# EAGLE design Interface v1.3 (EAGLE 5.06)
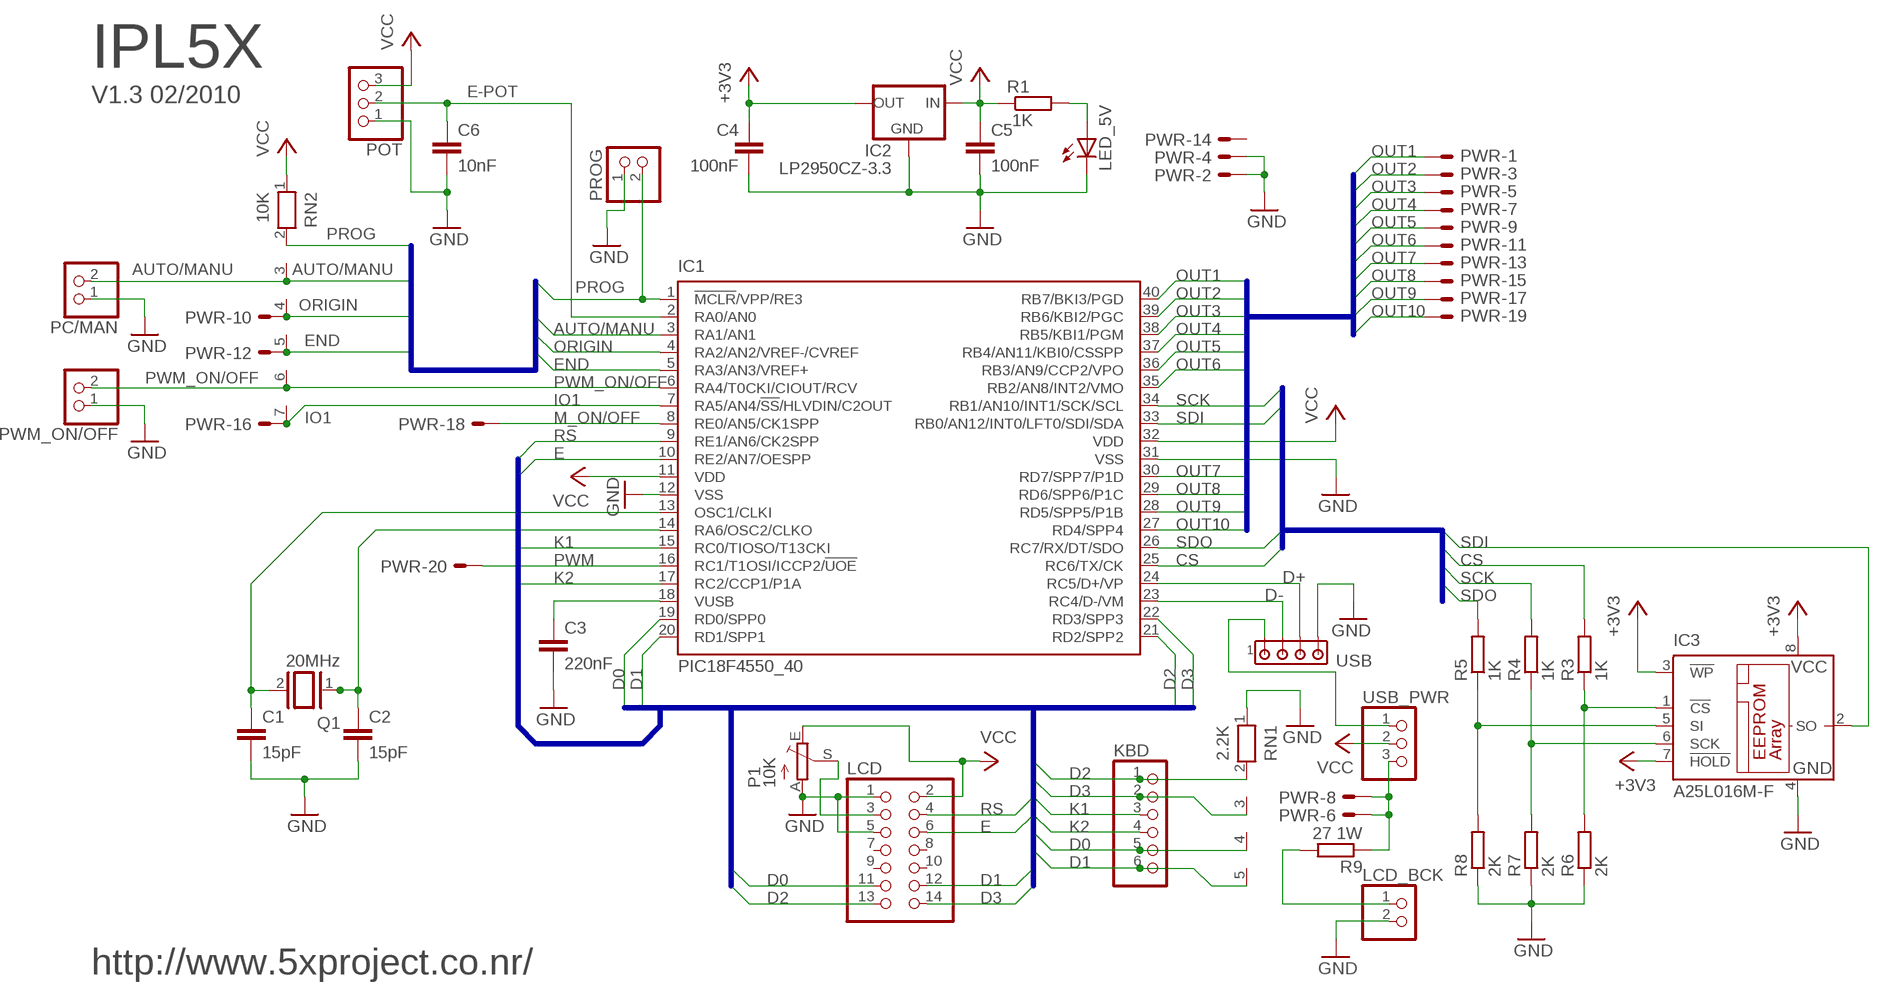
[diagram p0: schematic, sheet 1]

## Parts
C1  15pF  C-EU025-024X044  [C025-024X044]
C2  15pF  C-EU025-024X044  [C025-024X044]
C3  220nF  C-EU050-030X075  [C050-030X075]
C4  100nF  C-EU075-032X103  [C075-032X103]
C5  100nF  C-EU050-030X075  [C050-030X075]
C6  10nF  C-EU050-030X075  [C050-030X075]
IC1  PIC18F4550_40  [DIL40]
IC2  LP2950CZ-3.3  LP2950ACZ-3.3  [TO92]
IC3  A25L016M-F  25LC080SN  [SO-08]
KBD  PINHD-1X6  [1X06]
LCD  PINHD-2X7  [2X07]
LCD_BCK  PINHD-1X2  [1X02]
LED_5V  LED5MM  [LED5MM]
P1  10K  TRIM_EU-LI10  [LI10]
PC/MAN  PINHD-1X2  [1X02]
POT  PINHD-1X3  [1X03]
PROG  PINHD-1X2  [1X02]
PWM_ON/OFF  PINHD-1X2  [1X02]
PWR  ML20E  [ML20]
Q1  20MHz  XTAL/S  [QS]
R1  1K  R-EU_0207/10  [0207/10]
R3  1K  R-EU_0207/10  [0207/10]
R4  1K  R-EU_0207/10  [0207/10]
R5  1K  R-EU_0207/10  [0207/10]
R6  2K  R-EU_0204/7  [0204/7]
R7  2K  R-EU_0204/7  [0204/7]
R8  2K  R-EU_0204/7  [0204/7]
R9  27 1W  R-EU_0207/12  [0207/12]
RN1  2.2K  RN04  [RN-5]
RN2  10K  RN06  [RN-7]
USB  MTA04-100  [10X04MTA]
USB_PWR  PINHD-1X3  [1X03]

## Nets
+3V3: C4.1 IC2.1(OUT) IC3.3(!WP) IC3.7(!HOLD) IC3.8(VCC)
AUTO/MANU: IC1.3(RA1/AN1) PC/MAN.2 RN2.3
CS: IC1.25(RC6/TX/CK) R3.2
D0: IC1.19(RD0/SPP0) KBD.5 LCD.11 RN1.4
D1: IC1.20(RD1/SPP1) KBD.6 LCD.12 RN1.5
D2: IC1.21(RD2/SPP2) KBD.1 LCD.13 RN1.2
D3: IC1.22(RD3/SPP3) KBD.2 LCD.14 RN1.3
D+: IC1.24(RC5/D+/VP) USB.3
D-: IC1.23(RC4/D-/VM) USB.2
E: IC1.10(RE2/AN7/OESPP) LCD.6
E-POT: C6.1 IC1.2(RA0/AN0) POT.2
END: IC1.5(RA3/AN3/VREF+) PWR.12 RN2.5
GND: C1.2 C2.2 C3.2 C4.2 C5.2 C6.2 IC1.12(VSS) IC1.31(VSS) IC2.2(GND) IC3.4(GND) LCD.1 LCD.5 LCD_BCK.2 LED_5V.K(C) P1.A PC/MAN.1 POT.1 PROG.1 PWM_ON/OFF.1 PWR.2 PWR.4 R6.1 R7.1 R8.1 RN1.1 USB.4
IO1: IC1.7(RA5/AN4/!SS!/HLVDIN/C2OUT) PWR.16 RN2.7
K1: IC1.15(RC0/TIOSO/T13CKI) KBD.3
K2: IC1.17(RC2/CCP1/P1A) KBD.4
M_ON/OFF: IC1.8(RE0/AN5/CK1SPP) PWR.18
N$1: C2.1 IC1.14(RA6/OSC2/CLKO) Q1.1
N$2: C1.1 IC1.13(OSC1/CLKI) Q1.2
N$5: PWR.6 PWR.8 R9.1 USB_PWR.3
N$6: LED_5V.A R1.2
N$7: C3.1 IC1.18(VUSB)
N$8: IC3.1(!CS) R3.1 R6.2
N$10: IC3.6(SCK) R4.1 R7.2
N$11: USB.1 USB_PWR.1
N$12: LCD_BCK.1 R9.2
N$14: IC3.5(SI) R5.1 R8.2
N$16: LCD.3 P1.S
ORIGIN: IC1.4(RA2/AN2/VREF-/CVREF) PWR.10 RN2.4
OUT1: IC1.40(RB7/BKI3/PGD) PWR.1
OUT2: IC1.39(RB6/KBI2/PGC) PWR.3
OUT3: IC1.38(RB5/KBI1/PGM) PWR.5
OUT4: IC1.37(RB4/AN11/KBI0/CSSPP) PWR.7
OUT5: IC1.36(RB3/AN9/CCP2/VPO) PWR.9
OUT6: IC1.35(RB2/AN8/INT2/VMO) PWR.11
OUT7: IC1.30(RD7/SPP7/P1D) PWR.13
OUT8: IC1.29(RD6/SPP6/P1C) PWR.15
OUT9: IC1.28(RD5/SPP5/P1B) PWR.17
OUT10: IC1.27(RD4/SPP4) PWR.19
PROG: IC1.1(!MCLR!/VPP/RE3) PROG.2 RN2.2
PWM: IC1.16(RC1/T1OSI/ICCP2/!UOE) PWR.20
PWM_ON/OFF: IC1.6(RA4/T0CKI/CIOUT/RCV) PWM_ON/OFF.2 RN2.6
RS: IC1.9(RE1/AN6/CK2SPP) LCD.4
SCK: IC1.34(RB1/AN10/INT1/SCK/SCL) R4.2
SDI: IC1.33(RB0/AN12/INT0/LFT0/SDI/SDA) IC3.2(SO)
SDO: IC1.26(RC7/RX/DT/SDO) R5.2
VCC: C5.1 IC1.11(VDD) IC1.32(VDD) IC2.3(IN) LCD.2 P1.E POT.3 R1.1 RN2.1 USB_PWR.2
Unconnected: LCD.7 LCD.8 LCD.9 LCD.10 PWR.14

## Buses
OUT1,OUT2,OUT3,OUT4,OUT5,OUT6,OUT7,OUT8,OUT9,OUT10
SDI,SDO,SCK,CS
PROG,AUTO/MANU,ORIGIN,END,M_ON/OFF
D0,D1,D2,D3,E,RS,K1,K2

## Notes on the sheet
- IPL5X
- V1.3 02/2010
- http://www.5xproject.co.nr/

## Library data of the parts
C1-C6 = rcl:C-EU: CAPACITOR, European symbol
IC1 = microchip:PIC18F4*_40: USB Microcontrollers with nanoWatt Technology High-Performance, Enhanced Flash, 28/40/44-Pin, Source: http://ww1.microchip.com/downloads/en/devicedoc/39632c.pdf
IC2 = v-reg:LP2950?*: Source: http://cache.national.com/ds/LP/LP2950.pdf
IC3 = microchip:25*: Serial EEPROM 4 K, SPI bus
KBD = pinhead:PINHD-1X6: PIN HEADER
LCD = pinhead:PINHD-2X7: PIN HEADER
LCD_BCK PC/MAN PROG PWM_ON/OFF = pinhead:PINHD-1X2: PIN HEADER
LED_5V = led:LED: LED
P1 = pot:TRIM_EU-: POTENTIOMETER
POT USB_PWR = pinhead:PINHD-1X3: PIN HEADER
PWR = con-harting-ml:ML20?E: HARTING
Q1 = special:XTAL/S: CRYSTAL
R1 R3-R9 = rcl:R-EU_: RESISTOR, European symbol
RN1 = resistor-net:RN04: RESISTOR NETWORK
RN2 = resistor-net:RN06: RESISTOR NETWORK
USB = con-amp:MTA04-100: AMP connector

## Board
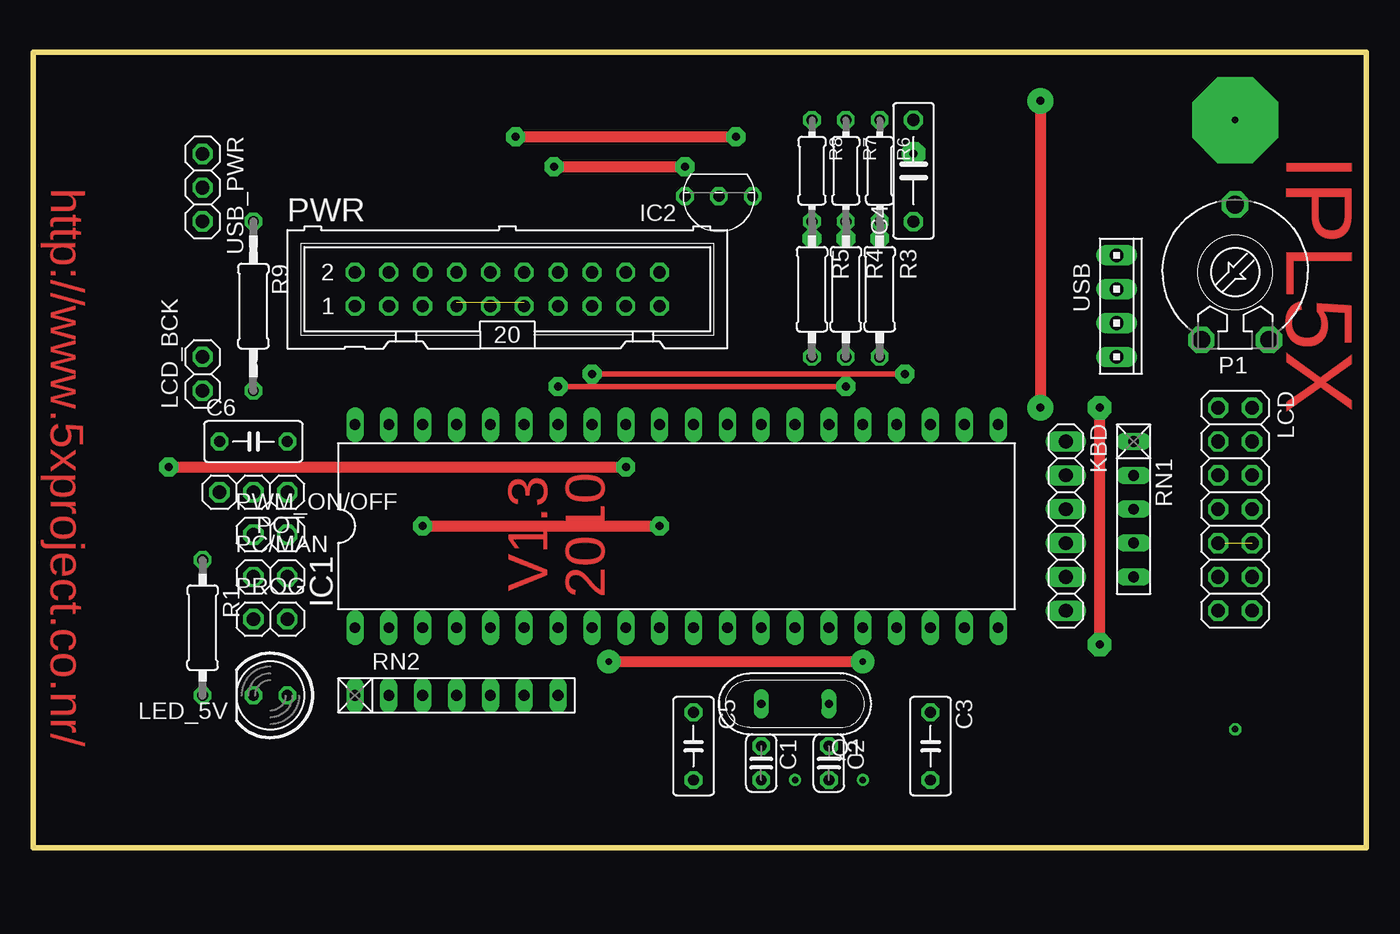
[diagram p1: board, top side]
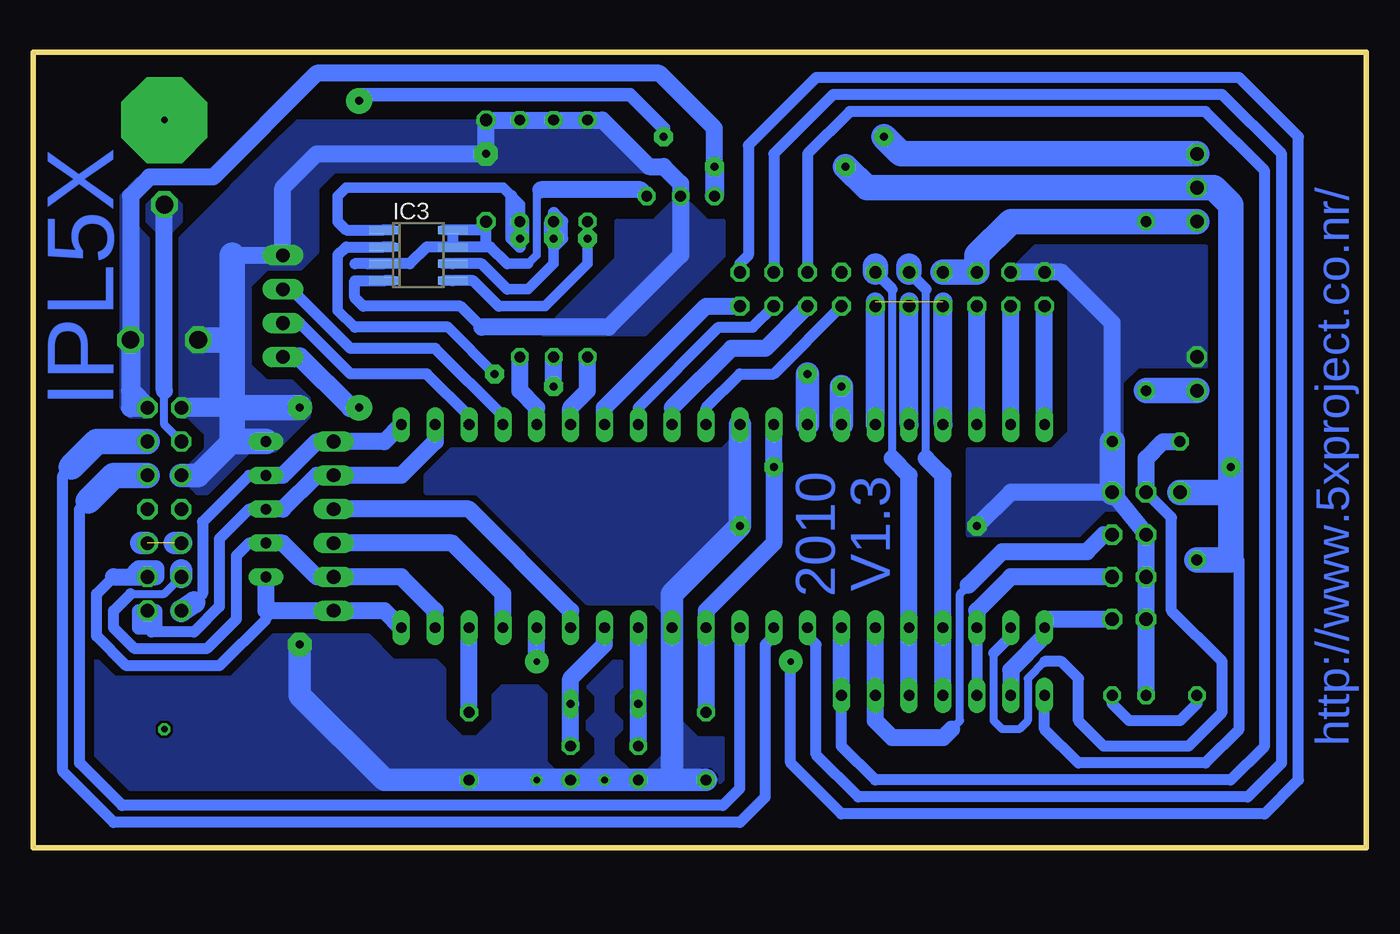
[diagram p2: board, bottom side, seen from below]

Size 100 x 59.68 mm. Coordinates in mm from the lower left corner, seen from the top.
Outline: 0,0 100,0 100,59.68 0,59.68 0,0
Copper layers (1*16): Top 0.035mm / dielectric 1.5mm / Bottom 0.035mm
Design rules "default": minimum track width 10mil, minimum drill 24mil, track to track 8mil, track to pad 8mil, pad to pad 8mil, via to via 8mil, smd to smd 8mil, copper to edge 40mil, drill to drill 8mil, minimum pad ring 10mil, minimum via ring 8mil, stop-mask expansion 4mil, vias tented up to drill 0mil, thermal gap 10mil

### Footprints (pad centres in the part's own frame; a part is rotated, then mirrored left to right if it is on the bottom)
C025-024X044 = drill 0.813 octagon: 1 -1.27,0; 2 1.27,0
C050-030X075 = drill 0.813 octagon: 1 -2.54,0; 2 2.54,0
C075-032X103 = drill 0.914 octagon: 1 -3.81,0; 2 3.81,0
DIL40 = drill 0.813 long: 1 -24.13,-7.62; 2 -21.59,-7.62; 3 -19.05,-7.62; 4 -16.51,-7.62; 5 -13.97,-7.62; 6 -11.43,-7.62; 7 -8.89,-7.62; 8 -6.35,-7.62; 9 -3.81,-7.62; 10 -1.27,-7.62; 11 1.27,-7.62; 12 3.81,-7.62; 13 6.35,-7.62; 14 8.89,-7.62; 15 11.43,-7.62; 16 13.97,-7.62; 17 16.51,-7.62; 18 19.05,-7.62; 19 21.59,-7.62; 20 24.13,-7.62; 21 24.13,7.62; 22 21.59,7.62; 23 19.05,7.62; 24 16.51,7.62; 25 13.97,7.62; 26 11.43,7.62; 27 8.89,7.62; 28 6.35,7.62; 29 3.81,7.62; 30 1.27,7.62; 31 -1.27,7.62; 32 -3.81,7.62; 33 -6.35,7.62; 34 -8.89,7.62; 35 -11.43,7.62; 36 -13.97,7.62; 37 -16.51,7.62; 38 -19.05,7.62; 39 -21.59,7.62; 40 -24.13,7.62
TO92 = drill 0.813 octagon: 1 -2.54,0; 2 0,0; 3 2.54,0
SO-08 = smd 0.6 x 2.2: 1 -1.905,-2.6; 2 -0.635,-2.6; 3 0.635,-2.6; 4 1.905,-2.6; 5 1.905,2.6; 6 0.635,2.6; 7 -0.635,2.6; 8 -1.905,2.6
1X06 = drill 1.016 long: 1 -6.35,0; 2 -3.81,0; 3 -1.27,0; 4 1.27,0; 5 3.81,0; 6 6.35,0
2X07 = drill 1.016 octagon: 1 -7.62,-1.27; 2 -7.62,1.27; 3 -5.08,-1.27; 4 -5.08,1.27; 5 -2.54,-1.27; 6 -2.54,1.27; 7 0,-1.27; 8 0,1.27; 9 2.54,-1.27; 10 2.54,1.27; 11 5.08,-1.27; 12 5.08,1.27; 13 7.62,-1.27; 14 7.62,1.27
1X02 = drill 1.016 octagon: 1 -1.27,0; 2 1.27,0
LED5MM = drill 0.813 octagon: A -1.27,0; K 1.27,0
LI10 = drill 1.321 octagon: A -2.54,-5.08; E 2.54,-5.08; S 0,5.08
1X03 = drill 1.016 octagon: 1 -2.54,0; 2 0,0; 3 2.54,0
ML20 = drill 0.914 octagon: 1 -11.43,-1.27; 2 -11.43,1.27; 3 -8.89,-1.27; 4 -8.89,1.27; 5 -6.35,-1.27; 6 -6.35,1.27; 7 -3.81,-1.27; 8 -3.81,1.27; 9 -1.27,-1.27; 10 -1.27,1.27; 11 1.27,-1.27; 12 1.27,1.27; 13 3.81,-1.27; 14 3.81,1.27; 15 6.35,-1.27; 16 6.35,1.27; 17 8.89,-1.27; 18 8.89,1.27; 19 11.43,-1.27; 20 11.43,1.27
QS = drill 0.61 long: 1 -2.54,0; 2 2.54,0
0207/10 = drill 0.813 octagon: 1 -5.08,0; 2 5.08,0
0204/7 = drill 0.813 octagon: 1 -3.81,0; 2 3.81,0
0207/12 = drill 0.813 octagon: 1 -6.35,0; 2 6.35,0
RN-5 = drill 0.813 long: 1 -5.08,0; 2 -2.54,0; 3 0,0; 4 2.54,0; 5 5.08,0
RN-7 = drill 0.813 long: 1 -7.62,0; 2 -5.08,0; 3 -2.54,0; 4 0,0; 5 2.54,0; 6 5.08,0; 7 7.62,0
10X04MTA = drill 1.016 long: 1 3.81,0; 2 1.27,0; 3 -1.27,0; 4 -3.81,0

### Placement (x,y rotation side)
C1  54.61,6.35 270 top
C2  59.69,6.35 270 top
C3  67.31,7.62 270 top
C4  66.04,50.8 90 top
C5  49.53,7.62 270 top
C6  16.51,30.48 0 top
IC1  48.26,24.13 0 top
IC2  51.44,48.9 180 top
IC3  71.12,44.45 270 bottom
KBD  77.47,24.13 270 top
LCD  90.17,25.4 270 top
LCD_BCK  12.7,35.56 90 top
LED_5V  17.78,11.43 180 top
P1  90.17,43.18 0 top
PC/MAN  17.78,20.32 0 top
POT  16.51,26.67 180 top
PROG  17.78,17.14 0 top
PWM_ON/OFF  17.78,23.5 0 top
PWR  35.56,41.91 0 top
Q1  57.15,10.79 180 top
R1  12.7,16.51 270 top
R3  63.5,41.91 270 top
R4  60.96,41.91 270 top
R5  58.42,41.91 270 top
R6  63.5,50.8 270 top
R7  60.96,50.8 270 top
R8  58.42,50.8 270 top
R9  16.51,40.64 270 top
RN1  82.55,25.4 270 top
RN2  31.75,11.43 0 top
USB  81.28,40.64 270 top
USB_PWR  12.7,49.53 270 top

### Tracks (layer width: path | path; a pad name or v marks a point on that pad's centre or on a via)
+3V3
  Bottom 0.61: 61.91,49.37 62.23,49.37 62.23,44.45 62.87,43.81
  Bottom 0.8: 62.87,43.81 64.45,43.81
  Bottom 0.813: IC3.7 IC3.8 | IC3.7 70.48,45.09 71.75,43.81 74.93,43.81 | 74.93,43.81 IC3.3 | 64.45,43.81 65.72,45.09 | 65.72,45.09 IC3.7 | 65.72,45.09 66.04,45.09 C4.1 | 74.93,43.81 75.88,43.81
  Bottom 1.27: IC2.1 54.45,49.37 61.91,49.37
AUTO/MANU
  Bottom 0.813: IC1.3 RN2.3
  Bottom 1.27: IC1.3 29.21,17.78 26.67,20.32 PC/MAN.2
CS
  Bottom 1.27: IC1.25 62.23,33.02 63.5,34.29 R3.2
D0
  Bottom 0.61: 92.71,19.05 90.17,19.05 LCD.11
  Bottom 0.813: 92.71,19.05 93.98,17.78 93.98,16.51 92.39,14.92 87,14.92 84.77,17.14 84.77,21.91 83.82,22.86 RN1.4
  Bottom 1.27: IC1.19 69.85,17.78 72.39,20.32 KBD.5 78.74,20.32 81.28,22.86 RN1.4
  Bottom 1.676: LCD.11 88.9,20.8
D1
  Bottom 0.813: 93.98,20.32 95.25,19.05 95.25,15.88 93.03,13.65 86.04,13.65 82.55,17.14 82.55,17.78
  Bottom 1.27: 92.71,20.32 92.08,20.32 90.81,20.32 90.81,20.95 92.08,20.95 92.71,20.32 | IC1.20 73.66,17.78 KBD.6 82.55,17.78 RN1.5 | 92.71,20.32 LCD.12 | 93.98,20.32 92.71,20.32
D2
  Bottom 0.813: RN1.2 83.82,27.94 87.31,24.45 87.31,19.05 87.95,18.41
  Bottom 1.27: IC1.21 73.66,30.48 KBD.1 78.74,30.48 81.28,27.94 RN1.2
  Bottom 1.676: 87.95,18.41 LCD.13
D3
  Bottom 0.813: 90.81,16.51 91.12,16.19 87.95,16.19 86.04,18.1 86.04,23.18 83.82,25.4 RN1.3
  Bottom 1.016: 90.81,16.51 92.08,16.51 92.08,17.78 LCD.14 90.81,17.78 90.81,16.51
  Bottom 1.27: IC1.22 69.85,30.48 72.39,27.94 KBD.2 78.74,27.94 81.28,25.4 RN1.3
D+
  Bottom 0.406: IC1.24 64.77,32.38
  Bottom 0.813: 64.77,32.38 69.85,37.47 76.2,37.47 80.64,41.91 USB.3
D-
  Bottom 0.813: USB.2 80.01,39.37 76.2,35.56 70.48,35.56 67.31,32.38 IC1.23
E
  Bottom 0.813: IC1.10 46.99,4.45 48.26,3.17 93.34,3.17 96.52,6.35 96.52,25.4 95.89,26.04
  Bottom 1.93: 95.89,26.04 93.98,27.94 LCD.6
E-POT
  Bottom 0.61: 24.13,13.97 25.4,12.7 25.4,9.53 26.04,8.89 27.3,8.89 27.94,9.53 27.94,14.61
  Bottom 0.813: 27.94,14.61 26.67,15.88 IC1.2 | POT.2 14.61,24.77 14.61,17.78 10.79,13.97 10.79,10.16 13.34,7.62 19.68,7.62 21.59,9.53 21.59,12.7 22.86,13.97 24.13,13.97
  Bottom 1.27: POT.2 16.51,27.94 16.51,29.21 15.24,30.48 C6.1
END
  Bottom 0.61: 35.56,29.21 35.56,41.91
  Bottom 0.813: 35.56,41.91 PWR.12
  Bottom 1.27: 35.56,29.21 34.29,27.94 IC1.5 RN2.5
  Bottom 1.93: PWR.12 36.83,43.66
GND  (via drill 0.5 pad 0.3, 0.6 pad 1.42, 0.6 pad 1.78)
  Top 0.813: v29.21,24.13 v46.99,24.13 | v80.01,15.24 v80.01,33.02
  Bottom 0.813: IC3.4 75.88,42.55 75.88,41.27 75.25,40.64 67.94,40.64 66.36,39.05
  Bottom 1.27: LED_5V.K PROG.1 PC/MAN.1 PWM_ON/OFF.1 POT.1 26.67,26.67 v29.21,24.13 | C6.2 19.05,39.37 22.86,43.18 PWR.2 PWR.4 | 66.36,39.05 56.83,39.05 51.44,44.45 IC2.2 51.44,49.85 52.7,51.12 53.82,51.12 57.31,54.61 R8.1 R7.1 R6.1 C4.2 v66.04,52.07 78.74,52.07 81.28,49.53 USB.4 85.09,44.45
  Bottom 1.422: 85.09,33.02 LCD.1
  Bottom 1.676: 52.07,5.08 IC1.12 52.07,19.05 v46.99,24.13 IC1.31 | 52.07,5.08 C5.2 | 52.07,5.08 C1.2 v57.15,5.08 C2.2 v62.23,5.08 C3.2 73.66,5.08 80.01,11.43 v80.01,15.24
  Bottom 1.778: 85.09,30.48 87.63,27.94 LCD.5
  Bottom 1.93: 85.09,33.02 85.09,38.1 | 85.09,38.1 P1.A | v80.01,33.02 85.09,33.02 | 85.09,33.02 85.09,30.48 RN1.1 | 85.09,38.1 85.09,44.45 | POT.1 C6.2
  pour Bottom (no thermals): 92.71,4.45 59.69,4.45 61.59,6.35 61.59,11.43 62.23,12.06 64.77,12.06 65.41,11.43 65.41,9.53 66.67,8.26 67.94,8.26 69.22,9.53 69.22,13.34 69.85,13.97 73.03,13.97 74.93,15.88 81.92,15.88 85.09,12.7 93.98,12.7 95.25,13.97 95.25,6.99
  pour Bottom (no thermals): 46.99,24.13 46.99,31.11 48.26,29.84 68.58,29.84 70.48,27.94 70.48,26.67 66.67,26.67 58.42,18.41 53.34,18.41 52.07,17.14 52.07,19.05
  pour Bottom (no thermals): 83.82,36.2 83.82,42.23 82.55,43.5 81.28,43.5 81.28,53.34 88.9,45.72 88.9,32.38 88.27,32.38 87,31.11 87,29.84 88.27,28.57 88.27,27.3 87.63,26.67 87,26.67 83.82,29.84 81.92,29.84 79.38,32.38 79.38,33.66 80.64,34.92 82.55,34.92
  pour Bottom (no thermals): 53.34,50.8 77.47,50.8 78.74,49.53 78.74,44.77 80.01,43.5 81.28,43.5 81.28,53.34 80.17,54.45 57.31,54.45 55.88,53.34
  pour Bottom (no thermals): 51.44,48.9 49.53,46.99 48.26,46.99 48.26,44.45 54.13,38.58 61.75,38.58 56.2,44.13 56.2,46.99 53.34,46.99
  pour Bottom (no thermals): 26.67,43.18 24.77,45.09 12.06,45.09 12.06,36.2 17.14,36.2 18.41,34.92 18.41,25.4 19.68,25.4 21.59,23.5 29.84,23.5 29.84,29.84 23.5,29.84 22.23,31.11 22.23,41.91 23.5,43.18
  pour Bottom: 56.52,6.99 56.52,8.26 55.88,8.89 55.88,9.53 56.52,10.16 56.52,11.43 55.88,12.06 55.88,13.97 56.52,13.97 58.42,12.06 57.78,11.43 57.78,10.16 58.42,9.53 58.42,8.89 57.78,8.26 57.78,6.99 59.05,5.71 59.05,4.45 55.24,4.45 55.24,5.71
  pour Bottom: 53.98,4.45 48.9,4.45 48.26,5.08 48.26,8.26 50.16,8.26 51.44,9.53 52.7,9.53 52.7,6.99 53.98,5.71
IO1  (via drill 0.6 pad 1.02)
  Bottom 0.813: PWR.16 41.91,52.07 38.73,55.24 12.06,55.24 7.62,50.8 7.62,7.62 10.16,5.08 36.83,5.08 39.37,7.62 RN2.7
  Bottom 1.27: RN2.7 IC1.7
  other vias: 39.37,11.43
K1
  Bottom 1.27: IC1.15 59.69,17.78 67.31,25.4 KBD.3
K2
  Bottom 1.27: IC1.17 64.77,19.05 68.58,22.86 KBD.4
M_ON/OFF
  Bottom 0.813: IC1.8 41.91,15.88 41.27,15.24 41.27,6.99 38.1,3.81 8.89,3.81 6.35,6.35 6.35,52.07 10.79,56.52 40.01,56.52 44.45,52.07 PWR.18
N$1
  Bottom 1.27: C2.1 Q1.1 59.69,12.7 57.15,15.24 IC1.14
N$2
  Bottom 1.27: IC1.13 Q1.2 C1.1
N$3  (1 unrouted)
  Bottom 1.676: 89.38,22.86 88.9,22.86 | 91.92,22.86 91.44,22.86
N$4  (2 unrouted)
  Bottom 1.422: 31.75,40.96 31.75,40.64 | 34.29,40.96 34.29,40.64 | 36.83,40.96 36.83,40.64
N$5
  Bottom 1.93: USB_PWR.3 R9.1 26.67,46.99 29.21,44.45 PWR.6 PWR.8
N$6
  Bottom 0.813: R1.2 12.7,10.79 13.97,9.53 17.78,9.53 19.05,10.79 LED_5V.A
N$7
  Bottom 1.27: C3.1 IC1.18
N$8  (via drill 0.6 pad 1.42)
  Bottom 0.8: 77.15,46.99 77.15,48.9 76.52,49.53 64.77,49.53 64.14,48.9 63.5,48.26 R3.1
  Bottom 0.813: IC3.1 76.52,46.35 77.15,46.99
  Bottom 0.9: 64.14,45.72 v63.5,45.72 | 64.14,45.72 64.14,48.9 | 63.5,45.09 64.14,45.72
  Bottom 1.422: v63.5,45.72 R3.1
N$9
  Bottom 0.813: 68.58,42.55 69.22,42.55
N$10  (via drill 0.6 pad 1.42)
  Bottom 0.8: 64.45,41.91 62.87,41.91 60.96,43.81 60.96,45.09 v60.96,45.72
  Bottom 0.813: IC3.6 66.36,43.81 64.45,41.91
  Bottom 0.9: 60.96,45.09 60.33,45.72 60.33,46.99 60.96,47.62
  Bottom 1.422: v60.96,45.72 R4.1
N$11  (via drill 0.6 pad 1.42, 0.6 pad 1.93)
  Top 0.813: v36.2,53.34 v52.7,53.34 | v75.56,56.04 v75.56,33.02
  Bottom 1.016: v75.56,56.04 75.56,56.52 55.24,56.52 52.7,53.98 v52.7,53.34
  Bottom 1.422: USB.1 80.01,36.83 76.2,33.02 v75.56,33.02
  Bottom 1.93: USB_PWR.1 34.92,52.07 v36.2,53.34
N$12
  Bottom 1.93: LCD_BCK.1 R9.2
N$13  (via drill 0.5)
  other vias: 90.17,8.89
N$14  (via drill 0.6 pad 1.42)
  Bottom 0.61: v58.42,45.72 R5.1
  Bottom 0.8: 65.09,40.64 61.59,40.64 58.42,43.81 v58.42,45.72
  Bottom 0.813: IC3.5 66.99,42.55 65.09,40.64
N$15  (via drill 0.5 pad 6.45)
  other vias: 90.17,54.61
N$16
  Bottom 0.61: LCD.3 90.17,31.75 90.17,34.29
  Bottom 1.27: 90.17,34.29 P1.S
  pour Bottom (no thermals): 88.9,46.99 90.17,45.72 91.44,46.99 91.44,48.26 90.81,48.9 89.53,48.9 88.9,48.26
N$17
  Bottom 0.813: 66.04,46.35 69.22,46.35
N$18
  Bottom 0.813: 68.58,43.81 69.22,43.81
N$19
  Bottom 0.813: 73.03,42.55 73.66,42.55
N$20
  Bottom 0.813: 73.03,45.09 73.66,45.09
N$21
  Bottom 0.813: 73.03,46.35 73.66,46.35
N$22  (via drill 0.5 pad 1.78)
  other vias: 43.18,13.97
ORIGIN
  Bottom 0.61: 33.02,29.21 33.02,41.91
  Bottom 0.813: 33.02,41.91 PWR.10
  Bottom 1.27: 33.02,29.21 31.75,27.94 IC1.4 RN2.4
  Bottom 1.93: PWR.10 34.29,43.66
OUT1
  Bottom 1.27: IC1.40 PWR.1
OUT2
  Bottom 1.27: IC1.39 PWR.3
OUT3
  Bottom 1.27: IC1.38 PWR.5
OUT4
  Bottom 1.422: IC1.37 PWR.7
OUT5
  Bottom 1.422: IC1.36 PWR.9
OUT6
  Bottom 1.422: IC1.35 PWR.11
OUT7
  Bottom 0.813: IC1.30 49.53,33.02 46.99,35.56 44.45,35.56 PWR.13
OUT8
  Bottom 0.813: 52.07,33.02 IC1.29
  Bottom 1.27: 52.07,33.02 47.62,37.47 45.09,37.47 PWR.15
OUT9
  Bottom 0.813: PWR.17 46.04,39.05 48.58,39.05 54.61,33.02 IC1.28
OUT10
  Bottom 1.27: PWR.19 49.53,40.64 57.15,33.02 IC1.27
PROG
  Bottom 1.27: RN2.2 26.67,13.34 24.13,15.88 | PROG.2 24.13,17.14 24.13,15.88 | 24.13,15.88 IC1.1
PWM  (via drill 0.5 pad 1.78)
  Top 0.813: v43.18,13.97 v62.23,13.97
  Bottom 0.813: PWR.20 46.99,43.81 46.35,44.45 46.35,52.7 41.27,57.78 9.53,57.78 5.08,53.34 5.08,5.08 7.62,2.54 39.37,2.54 43.18,6.35 v43.18,13.97
  Bottom 1.27: v62.23,13.97 IC1.16
PWM_ON/OFF  (via drill 0.6)
  Bottom 0.61: 29.84,19.68 30.48,19.05 30.48,9.53 31.11,8.89
  Bottom 1.27: IC1.6 RN2.6 36.83,9.53 35.56,8.26 31.75,8.26 31.11,8.89 | PWM_ON/OFF.2 19.68,23.5 20.95,22.23 27.3,22.23 29.84,19.68
  other vias: 36.83,11.43
RS
  Bottom 0.813: IC1.9 44.45,15.88 45.09,15.24 45.09,3.81 46.99,1.91 93.98,1.91 97.79,5.71 97.79,27.94 97.16,28.57
  Bottom 1.93: 97.16,28.57 95.25,30.48 LCD.4
SCK  (via drill 0.6 pad 1.42)
  Top 0.406: v39.37,34.61 v60.96,34.61
  Bottom 1.27: v60.96,34.61 R4.2
  Bottom 1.778: IC1.34 v39.37,34.61
SDI  (via drill 0.6 pad 1.42)
  Top 0.406: v41.91,35.56 v65.41,35.56
  Bottom 0.8: 77.15,44.45 77.15,40.32 75.88,39.05 | v65.41,35.56 68.9,39.05
  Bottom 0.813: 77.15,44.45 76.52,45.09 IC3.2 | 68.9,39.05 75.88,39.05
  Bottom 1.778: IC1.33 v41.91,35.56
SDO
  Bottom 1.27: IC1.26 59.69,33.02 58.42,34.29 R5.2
VCC  (via drill 0.6 pad 1.42)
  Top 0.813: v10.16,28.57 v44.45,28.57 | v39.05,51.12 v48.9,51.12
  Bottom 0.813: RN2.1 24.13,8.89 21.59,6.35 12.06,6.35 9.53,8.89 9.53,21.59 10.16,21.59
  Bottom 1.27: IC1.32 v44.45,28.57 44.45,22.86 49.53,17.78 IC1.11 C5.1 | P1.E 92.71,48.9 91.28,50.32 86.52,50.32 78.74,58.1 53.02,58.1 48.9,53.98 v48.9,51.12
  Bottom 1.422: 92.71,34.29 LCD.2 92.71,33.02 92.71,34.29 | P1.E 92.71,34.29 | v48.9,51.12 IC2.3
  Bottom 1.93: 10.16,26.67 POT.3 | v39.05,51.12 37.47,49.53 USB_PWR.2 11.43,49.53 10.16,48.26 v10.16,28.57 10.16,26.67 | R1.1 10.16,21.59 10.16,26.67
  pour Bottom (no thermals): 92.71,46.99 91.44,45.72 91.44,32.38 92.71,32.38 93.34,33.02 93.34,48.9 92.08,50.16 92.08,48.9 92.71,48.26

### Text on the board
Top: IPL5X | http://www.5xproject.co.nr/ | V1.3 | 2010
Bottom: IPL5X | V1.3 | 2010 | http://www.5xproject.co.nr/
